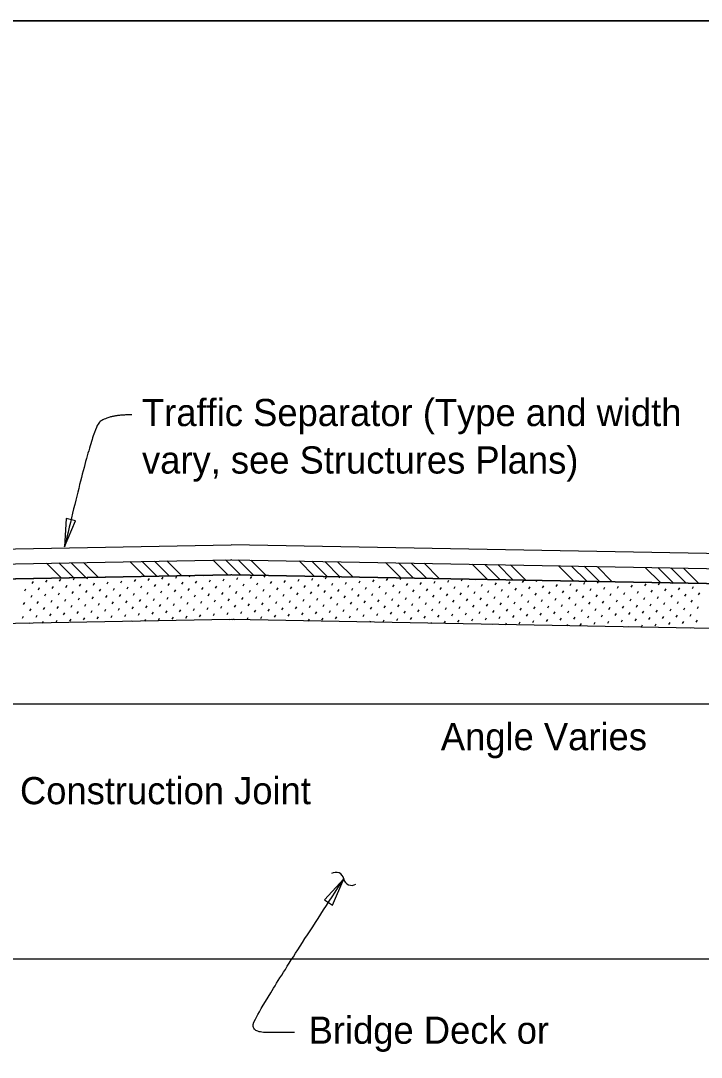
# Model space of a CAD drawing. Extents: x 0 to 15.4, y 0 to 9.7.
# Drawn here: x 7.109 to 9.001, y 6.847 to 9.73 of the extents above; entities that cross this region are included whole.
import ezdxf

# ---------------------------------------------------------------- set-up
doc = ezdxf.new("R2010")
doc.units = 0
for name, color, linetype in [('Dimension', 7, 'Continuous'), ('Miscellaneous', 7, 'Continuous'), ('Miscellaneous1', 7, 'Continuous'), ('SupstrConc', 7, 'Continuous'), ('SupstrConc_h', 7, 'Continuous'), ('TextStructures', 7, 'Continuous')]:
    doc.layers.add(name, color=color, linetype=linetype)

msp = doc.modelspace()

# ---------------------------------------------------------------- linework, layer by layer
at = {"layer": 'Dimension'}
for points in [[(7.2306, 8.266), (7.2611, 8.3391), (7.2353, 8.345)], [(8.007, 7.3426), (7.9531, 7.2845), (7.9753, 7.27)]]:
    msp.add_lwpolyline(points, close=True, dxfattribs=at)
for centre, start, end in [((7.9848, 7.3385), 10.958, 122.6852), ((8.0287, 7.347), 190.958, 302.6852)]:
    msp.add_arc(centre, 0.0224, start, end, dxfattribs=at)
for points in [[(7.4176, 8.6335), (7.3472, 8.6335), (7.3054, 8.5895), (7.2306, 8.266)], [(7.8701, 6.9155), (7.8284, 6.9155), (7.7546, 6.9155), (7.7546, 6.9572), (8.007, 7.3426)]]:
    msp.add_open_spline(points, degree=2, dxfattribs=at)
at = {"layer": 'Miscellaneous'}
for p, q in [((6.2709, 8.2042), (7.6932, 8.2305)), ((7.1801, 8.221), (7.221, 8.1801)), ((7.2144, 8.2217), (7.2554, 8.1807)), ((7.2488, 8.2223), (7.2897, 8.1814)), ((7.2831, 8.2229), (7.3241, 8.182)), ((7.4119, 8.2253), (7.4529, 8.1844)), ((7.4463, 8.226), (7.4872, 8.185)), ((7.4806, 8.2266), (7.5216, 8.1857)), ((7.515, 8.2272), (7.5559, 8.1863)), ((7.6438, 8.2296), (7.6847, 8.1887)), ((7.6781, 8.2303), (7.72, 8.1884)), ((7.6948, 8.2305), (9.1171, 8.2042)), ((7.7132, 8.2302), (7.7557, 8.1877)), ((7.7488, 8.2295), (7.7913, 8.187)), ((7.8825, 8.2271), (7.925, 8.1846)), ((7.9181, 8.2264), (7.9606, 8.1839)), ((7.9538, 8.2257), (7.9963, 8.1833)), ((7.9894, 8.2251), (8.0319, 8.1826)), ((8.1231, 8.2226), (8.1656, 8.1801)), ((8.1587, 8.2219), (8.2012, 8.1795)), ((8.1944, 8.2213), (8.2369, 8.1788)), ((8.23, 8.2206), (8.2725, 8.1781)), ((8.3637, 8.2182), (8.4062, 8.1757)), ((8.3993, 8.2175), (8.4418, 8.175)), ((7.6925, 8.1888), (6.2925, 8.1629)), ((6.2925, 8.1629), (7.6925, 8.1888)), ((9.0955, 8.1629), (7.6955, 8.1888)), ((7.6955, 8.1888), (9.0955, 8.1629)), ((8.435, 8.2168), (8.4775, 8.1743)), ((8.4706, 8.2162), (8.5131, 8.1737)), ((8.6043, 8.2137), (8.6468, 8.1712)), ((8.6399, 8.213), (8.6824, 8.1705)), ((8.6756, 8.2124), (8.7181, 8.1699)), ((8.7112, 8.2117), (8.7537, 8.1692)), ((8.8449, 8.2092), (8.8874, 8.1667)), ((8.8805, 8.2086), (8.923, 8.1661)), ((8.9162, 8.2079), (8.9587, 8.1654)), ((8.9519, 8.2073), (8.9943, 8.1648)), ((7.1404, 8.1647), (7.1437, 8.1703)), ((7.1786, 8.1679), (7.1818, 8.1735)), ((7.2167, 8.1711), (7.22, 8.1767)), ((7.2549, 8.1744), (7.2581, 8.18)), ((7.2723, 8.1569), (7.2756, 8.1625)), ((7.293, 8.1776), (7.2953, 8.1815)), ((7.3105, 8.1602), (7.3137, 8.1658)), ((7.3312, 8.1809), (7.3319, 8.1821)), ((7.3487, 8.1634), (7.3519, 8.169)), ((7.3868, 8.1666), (7.39, 8.1722)), ((7.425, 8.1699), (7.4282, 8.1755)), ((7.4631, 8.1731), (7.4664, 8.1787)), ((7.4806, 8.1557), (7.4838, 8.1613)), ((7.5013, 8.1764), (7.5045, 8.182)), ((7.5187, 8.1589), (7.522, 8.1645)), ((7.5394, 8.1796), (7.5427, 8.1852)), ((7.5569, 8.1621), (7.5601, 8.1677)), ((7.5776, 8.1828), (7.5798, 8.1867)), ((7.595, 8.1654), (7.5983, 8.171)), ((7.6157, 8.1861), (7.6165, 8.1874)), ((7.6332, 8.1686), (7.6364, 8.1742)), ((7.6713, 8.1719), (7.6746, 8.1775)), ((7.6888, 8.1544), (7.692, 8.16)), ((7.7095, 8.1751), (7.7127, 8.1807)), ((7.727, 8.1577), (7.7302, 8.1633)), ((7.7477, 8.1784), (7.7509, 8.184)), ((7.7651, 8.1609), (7.7683, 8.1665)), ((7.7858, 8.1816), (7.789, 8.1871)), ((7.8033, 8.1641), (7.8065, 8.1697)), ((7.824, 8.1848), (7.8249, 8.1864)), ((7.8414, 8.1674), (7.8447, 8.173)), ((7.8796, 8.1706), (7.8828, 8.1762)), ((7.9177, 8.1739), (7.921, 8.1795)), ((7.9352, 8.1564), (7.9384, 8.162)), ((7.9559, 8.1771), (7.9591, 8.1827)), ((7.9733, 8.1596), (7.9766, 8.1652)), ((7.994, 8.1803), (7.9957, 8.1833)), ((8.0115, 8.1629), (8.0147, 8.1685)), ((8.0496, 8.1661), (8.0529, 8.1717)), ((8.0878, 8.1694), (8.091, 8.175)), ((8.126, 8.1726), (8.1292, 8.1782)), ((8.1434, 8.1552), (8.1467, 8.1607)), ((8.1641, 8.1758), (8.1666, 8.1801)), ((8.1816, 8.1584), (8.1848, 8.164)), ((8.2023, 8.1791), (8.2025, 8.1794)), ((8.2197, 8.1616), (8.223, 8.1672)), ((8.2579, 8.1649), (8.2611, 8.1705)), ((8.296, 8.1681), (8.2993, 8.1737)), ((8.3342, 8.1714), (8.3374, 8.1769)), ((8.3723, 8.1746), (8.3733, 8.1763)), ((8.3898, 8.1571), (8.393, 8.1627)), ((8.4279, 8.1604), (8.4312, 8.166)), ((8.4661, 8.1636), (8.4693, 8.1692)), ((8.5043, 8.1669), (8.5075, 8.1725)), ((8.5424, 8.1701), (8.5441, 8.1731)), ((8.598, 8.1559), (8.6013, 8.1615)), ((8.6362, 8.1591), (8.6394, 8.1647)), ((8.6743, 8.1624), (8.6776, 8.168)), ((8.7125, 8.1656), (8.715, 8.1699)), ((8.7506, 8.1689), (8.7509, 8.1693)), ((8.8062, 8.1546), (8.8095, 8.1602)), ((8.8444, 8.1579), (8.8476, 8.1635)), ((8.8826, 8.1611), (8.8858, 8.1667)), ((8.9207, 8.1644), (8.9217, 8.1661)), ((7.1197, 8.144), (7.123, 8.1496)), ((7.1372, 8.1265), (7.1404, 8.1321)), ((7.1579, 8.1472), (7.1611, 8.1528)), ((7.1753, 8.1297), (7.1786, 8.1353)), ((7.196, 8.1504), (7.1993, 8.156)), ((7.2135, 8.133), (7.2167, 8.1386)), ((7.2342, 8.1537), (7.2374, 8.1593)), ((7.2516, 8.1362), (7.2549, 8.1418)), ((7.2898, 8.1395), (7.293, 8.1451)), ((7.328, 8.1427), (7.3312, 8.1483)), ((7.3661, 8.1459), (7.3693, 8.1515)), ((7.3836, 8.1285), (7.3868, 8.1341)), ((7.4043, 8.1492), (7.4075, 8.1548)), ((7.4217, 8.1317), (7.425, 8.1373)), ((7.4424, 8.1524), (7.4457, 8.158)), ((7.4599, 8.135), (7.4631, 8.1406)), ((7.498, 8.1382), (7.5013, 8.1438)), ((7.5362, 8.1415), (7.5394, 8.147)), ((7.5743, 8.1447), (7.5776, 8.1503)), ((7.5918, 8.1272), (7.595, 8.1328)), ((7.6125, 8.1479), (7.6157, 8.1535)), ((7.6299, 8.1305), (7.6332, 8.1361)), ((7.6506, 8.1512), (7.6539, 8.1568)), ((7.6681, 8.1337), (7.6713, 8.1393)), ((7.7063, 8.137), (7.7095, 8.1426)), ((7.7444, 8.1402), (7.7477, 8.1458)), ((7.7826, 8.1434), (7.7858, 8.149)), ((7.8, 8.126), (7.8033, 8.1316)), ((7.8207, 8.1467), (7.824, 8.1523)), ((7.8382, 8.1292), (7.8414, 8.1348)), ((7.8589, 8.1499), (7.8621, 8.1555)), ((7.8763, 8.1325), (7.8796, 8.1381)), ((7.897, 8.1532), (7.9003, 8.1588)), ((7.9145, 8.1357), (7.9177, 8.1413)), ((7.9526, 8.1389), (7.9559, 8.1445)), ((7.9908, 8.1422), (7.994, 8.1478)), ((8.0289, 8.1454), (8.0322, 8.151)), ((8.0464, 8.128), (8.0496, 8.1336)), ((8.0671, 8.1487), (8.0703, 8.1543)), ((8.0846, 8.1312), (8.0878, 8.1368)), ((8.1053, 8.1519), (8.1085, 8.1575)), ((8.1227, 8.1345), (8.126, 8.1401)), ((8.1609, 8.1377), (8.1641, 8.1433)), ((8.199, 8.1409), (8.2023, 8.1465)), ((8.2372, 8.1442), (8.2404, 8.1498)), ((8.2546, 8.1267), (8.2579, 8.1323)), ((8.2753, 8.1474), (8.2786, 8.153)), ((8.2928, 8.13), (8.296, 8.1356)), ((8.3135, 8.1507), (8.3167, 8.1563)), ((8.3309, 8.1332), (8.3342, 8.1388)), ((8.3516, 8.1539), (8.3549, 8.1595)), ((8.3691, 8.1364), (8.3723, 8.142)), ((8.4072, 8.1397), (8.4105, 8.1453)), ((8.4454, 8.1429), (8.4486, 8.1485)), ((8.4629, 8.1255), (8.4661, 8.1311)), ((8.4836, 8.1462), (8.4868, 8.1518)), ((8.501, 8.1287), (8.5043, 8.1343)), ((8.5217, 8.1494), (8.525, 8.155)), ((8.5392, 8.1319), (8.5424, 8.1375)), ((8.5599, 8.1526), (8.5631, 8.1582)), ((8.5773, 8.1352), (8.5806, 8.1408)), ((8.6155, 8.1384), (8.6187, 8.144)), ((8.6536, 8.1417), (8.6569, 8.1473)), ((8.6918, 8.1449), (8.695, 8.1505)), ((8.7092, 8.1275), (8.7125, 8.1331)), ((8.7299, 8.1482), (8.7332, 8.1538)), ((8.7474, 8.1307), (8.7506, 8.1363)), ((8.7681, 8.1514), (8.7713, 8.157)), ((8.7856, 8.1339), (8.7888, 8.1395)), ((8.8237, 8.1372), (8.8269, 8.1428)), ((8.8619, 8.1404), (8.8651, 8.146)), ((8.9, 8.1437), (8.9033, 8.1493)), ((8.9175, 8.1262), (8.9207, 8.1318)), ((8.9382, 8.1469), (8.9414, 8.1525)), ((8.9556, 8.1294), (8.9589, 8.135)), ((8.9763, 8.1501), (8.9796, 8.1557)), ((8.9938, 8.1327), (8.997, 8.1383)), ((7.1165, 8.1058), (7.1197, 8.1114)), ((7.1546, 8.109), (7.1579, 8.1146)), ((7.1928, 8.1123), (7.196, 8.1179)), ((7.2309, 8.1155), (7.2342, 8.1211)), ((7.2484, 8.0981), (7.2516, 8.1037)), ((7.2691, 8.1188), (7.2723, 8.1244)), ((7.2866, 8.1013), (7.2898, 8.1069)), ((7.3073, 8.122), (7.3105, 8.1276)), ((7.3247, 8.1045), (7.328, 8.1101)), ((7.3454, 8.1252), (7.3487, 8.1308)), ((7.3629, 8.1078), (7.3661, 8.1134)), ((7.401, 8.111), (7.4043, 8.1166)), ((7.4392, 8.1143), (7.4424, 8.1199)), ((7.4566, 8.0968), (7.4599, 8.1024)), ((7.4773, 8.1175), (7.4806, 8.1231)), ((7.4948, 8.1001), (7.498, 8.1057)), ((7.5155, 8.1208), (7.5187, 8.1264)), ((7.5329, 8.1033), (7.5362, 8.1089)), ((7.5536, 8.124), (7.5569, 8.1296)), ((7.5711, 8.1065), (7.5743, 8.1121)), ((7.6092, 8.1098), (7.6125, 8.1154)), ((7.6474, 8.113), (7.6506, 8.1186)), ((7.6856, 8.1163), (7.6888, 8.1219)), ((7.703, 8.0988), (7.7063, 8.1044)), ((7.7237, 8.1195), (7.727, 8.1251)), ((7.7412, 8.102), (7.7444, 8.1076)), ((7.7619, 8.1227), (7.7651, 8.1283)), ((7.7793, 8.1053), (7.7826, 8.1109)), ((7.8175, 8.1085), (7.8207, 8.1141)), ((7.8556, 8.1118), (7.8589, 8.1174)), ((7.8938, 8.115), (7.897, 8.1206)), ((7.9112, 8.0976), (7.9145, 8.1031)), ((7.9319, 8.1182), (7.9352, 8.1238)), ((7.9494, 8.1008), (7.9526, 8.1064)), ((7.9701, 8.1215), (7.9733, 8.1271)), ((7.9876, 8.104), (7.9908, 8.1096)), ((8.0082, 8.1247), (8.0115, 8.1303)), ((8.0257, 8.1073), (8.0289, 8.1129)), ((8.0639, 8.1105), (8.0671, 8.1161)), ((8.102, 8.1138), (8.1053, 8.1194)), ((8.1402, 8.117), (8.1434, 8.1226)), ((8.1576, 8.0995), (8.1609, 8.1051)), ((8.1783, 8.1202), (8.1816, 8.1258)), ((8.1958, 8.1028), (8.199, 8.1084)), ((8.2165, 8.1235), (8.2197, 8.1291)), ((8.2339, 8.106), (8.2372, 8.1116)), ((8.2721, 8.1093), (8.2753, 8.1149)), ((8.3102, 8.1125), (8.3135, 8.1181)), ((8.3484, 8.1157), (8.3516, 8.1213)), ((8.3659, 8.0983), (8.3691, 8.1039)), ((8.3866, 8.119), (8.3898, 8.1246)), ((8.404, 8.1015), (8.4072, 8.1071)), ((8.4247, 8.1222), (8.4279, 8.1278)), ((8.4422, 8.1048), (8.4454, 8.1104)), ((8.4803, 8.108), (8.4836, 8.1136)), ((8.5185, 8.1113), (8.5217, 8.1168)), ((8.5566, 8.1145), (8.5599, 8.1201)), ((8.5741, 8.097), (8.5773, 8.1026)), ((8.5948, 8.1177), (8.598, 8.1233)), ((8.6122, 8.1003), (8.6155, 8.1059)), ((8.6329, 8.121), (8.6362, 8.1266)), ((8.6504, 8.1035), (8.6536, 8.1091)), ((8.6711, 8.1242), (8.6743, 8.1298)), ((8.6885, 8.1068), (8.6918, 8.1124)), ((8.7267, 8.11), (8.7299, 8.1156)), ((8.7649, 8.1132), (8.7681, 8.1188)), ((8.803, 8.1165), (8.8062, 8.1221)), ((8.8205, 8.099), (8.8237, 8.1046)), ((8.8412, 8.1197), (8.8444, 8.1253)), ((8.8586, 8.1023), (8.8619, 8.1079)), ((8.8793, 8.123), (8.8826, 8.1286)), ((8.8968, 8.1055), (8.9, 8.1111)), ((8.9349, 8.1087), (8.9382, 8.1143)), ((8.9731, 8.112), (8.9763, 8.1176)), ((7.1132, 8.0676), (7.1165, 8.0732)), ((7.1339, 8.0883), (7.1372, 8.0939)), ((7.1514, 8.0709), (7.1546, 8.0765)), ((7.1721, 8.0916), (7.1753, 8.0972)), ((7.1896, 8.0741), (7.1928, 8.0797)), ((7.2102, 8.0948), (7.2135, 8.1004)), ((7.2277, 8.0774), (7.2309, 8.083)), ((7.2659, 8.0806), (7.2691, 8.0862)), ((7.304, 8.0839), (7.3073, 8.0894)), ((7.3422, 8.0871), (7.3454, 8.0927)), ((7.3596, 8.0696), (7.3629, 8.0752)), ((7.3803, 8.0903), (7.3836, 8.0959)), ((7.3978, 8.0729), (7.401, 8.0785)), ((7.4185, 8.0936), (7.4217, 8.0992)), ((7.4359, 8.0761), (7.4392, 8.0817)), ((7.4741, 8.0794), (7.4773, 8.085)), ((7.5122, 8.0826), (7.5155, 8.0882)), ((7.5504, 8.0858), (7.5536, 8.0914)), ((7.5679, 8.0684), (7.5711, 8.074)), ((7.5886, 8.0891), (7.5918, 8.0947)), ((7.606, 8.0716), (7.6092, 8.0772)), ((7.6267, 8.0923), (7.6299, 8.0979)), ((7.6442, 8.0749), (7.6474, 8.0805)), ((7.6649, 8.0956), (7.6681, 8.1012)), ((7.6823, 8.0781), (7.6856, 8.0837)), ((7.7205, 8.0813), (7.7237, 8.0869)), ((7.7586, 8.0846), (7.7619, 8.0902)), ((7.7968, 8.0878), (7.8, 8.0934)), ((7.8142, 8.0704), (7.8175, 8.076)), ((7.8349, 8.0911), (7.8382, 8.0967)), ((7.8524, 8.0736), (7.8556, 8.0792)), ((7.8731, 8.0943), (7.8763, 8.0999)), ((7.8905, 8.0769), (7.8938, 8.0825)), ((7.9287, 8.0801), (7.9319, 8.0857)), ((7.9669, 8.0833), (7.9701, 8.0889)), ((8.005, 8.0866), (8.0082, 8.0922)), ((8.0225, 8.0691), (8.0257, 8.0747)), ((8.0432, 8.0898), (8.0464, 8.0954)), ((8.0606, 8.0724), (8.0639, 8.078)), ((8.0813, 8.0931), (8.0846, 8.0987)), ((8.0988, 8.0756), (8.102, 8.0812)), ((8.1195, 8.0963), (8.1227, 8.1019)), ((8.1369, 8.0788), (8.1402, 8.0844)), ((8.1751, 8.0821), (8.1783, 8.0877)), ((8.2132, 8.0853), (8.2165, 8.0909)), ((8.2307, 8.0679), (8.2339, 8.0735)), ((8.2514, 8.0886), (8.2546, 8.0942)), ((8.2688, 8.0711), (8.2721, 8.0767)), ((8.2895, 8.0918), (8.2928, 8.0974)), ((8.307, 8.0743), (8.3102, 8.0799)), ((8.3277, 8.095), (8.3309, 8.1006)), ((8.3452, 8.0776), (8.3484, 8.0832)), ((8.3833, 8.0808), (8.3866, 8.0864)), ((8.4215, 8.0841), (8.4247, 8.0897)), ((8.4596, 8.0873), (8.4629, 8.0929)), ((8.4771, 8.0699), (8.4803, 8.0755)), ((8.4978, 8.0906), (8.501, 8.0962)), ((8.5152, 8.0731), (8.5185, 8.0787)), ((8.5359, 8.0938), (8.5392, 8.0994)), ((8.5534, 8.0763), (8.5566, 8.0819)), ((8.5915, 8.0796), (8.5948, 8.0852)), ((8.6297, 8.0828), (8.6329, 8.0884)), ((8.6678, 8.0861), (8.6711, 8.0917)), ((8.6853, 8.0686), (8.6885, 8.0742)), ((8.706, 8.0893), (8.7092, 8.0949)), ((8.7235, 8.0718), (8.7267, 8.0774)), ((8.7442, 8.0925), (8.7474, 8.0981)), ((8.7616, 8.0751), (8.7649, 8.0807)), ((8.7823, 8.0958), (8.7856, 8.1014)), ((8.7998, 8.0783), (8.803, 8.0839)), ((8.8379, 8.0816), (8.8412, 8.0872)), ((8.8761, 8.0848), (8.8793, 8.0904)), ((8.9142, 8.088), (8.9175, 8.0936)), ((8.9317, 8.0706), (8.9349, 8.0762)), ((8.9524, 8.0913), (8.9556, 8.0969)), ((8.9698, 8.0738), (8.9731, 8.0794)), ((8.9905, 8.0945), (8.9938, 8.1001)), ((7.6901, 8.0638), (6.3571, 8.0391)), ((7.1326, 8.0534), (7.1339, 8.0558)), ((7.1692, 8.0541), (7.1721, 8.059)), ((7.207, 8.0567), (7.2102, 8.0623)), ((7.2452, 8.0599), (7.2484, 8.0655)), ((7.2833, 8.0632), (7.2866, 8.0688)), ((7.3215, 8.0664), (7.3247, 8.072)), ((7.4171, 8.0587), (7.4185, 8.061)), ((7.4538, 8.0594), (7.4566, 8.0643)), ((7.4915, 8.0619), (7.4948, 8.0675)), ((7.5297, 8.0651), (7.5329, 8.0707)), ((9.0309, 8.0391), (7.6979, 8.0638)), ((7.7015, 8.0637), (7.703, 8.0662)), ((7.7379, 8.0639), (7.7412, 8.0695)), ((7.7761, 8.0671), (7.7793, 8.0727)), ((7.8724, 8.0605), (7.8731, 8.0618)), ((7.9083, 8.0599), (7.9112, 8.065)), ((7.9462, 8.0626), (7.9494, 8.0682)), ((7.9843, 8.0659), (7.9876, 8.0715)), ((8.0791, 8.0567), (8.0813, 8.0605)), ((8.1162, 8.0581), (8.1195, 8.0637)), ((8.1544, 8.0614), (8.1576, 8.067)), ((8.1925, 8.0646), (8.1958, 8.0702)), ((8.25, 8.0535), (8.2514, 8.056)), ((8.2863, 8.0537), (8.2895, 8.0592)), ((8.3245, 8.0569), (8.3277, 8.0625)), ((8.3626, 8.0601), (8.3659, 8.0657)), ((8.4008, 8.0634), (8.404, 8.069)), ((8.4208, 8.0504), (8.4215, 8.0515)), ((8.4389, 8.0666), (8.4422, 8.0722)), ((8.4567, 8.0497), (8.4596, 8.0548)), ((8.4945, 8.0524), (8.4978, 8.058)), ((8.5327, 8.0556), (8.5359, 8.0612)), ((8.5708, 8.0589), (8.5741, 8.0645)), ((8.609, 8.0621), (8.6122, 8.0677)), ((8.6275, 8.0465), (8.6297, 8.0503)), ((8.6471, 8.0654), (8.6504, 8.071)), ((8.6646, 8.0479), (8.6678, 8.0535)), ((8.7028, 8.0511), (8.706, 8.0567)), ((8.7409, 8.0544), (8.7442, 8.06)), ((8.7791, 8.0576), (8.7823, 8.0632)), ((8.7984, 8.0434), (8.7998, 8.0458)), ((8.8172, 8.0609), (8.8205, 8.0665)), ((8.8347, 8.0434), (8.8379, 8.049)), ((8.8554, 8.0641), (8.8586, 8.0697)), ((8.8728, 8.0467), (8.8761, 8.0523)), ((8.8935, 8.0674), (8.8968, 8.0729)), ((8.911, 8.0499), (8.9142, 8.0555)), ((8.9491, 8.0531), (8.9524, 8.0587)), ((8.9873, 8.0564), (8.9905, 8.062)), ((8.9692, 8.0402), (8.9698, 8.0413))]:
    msp.add_line(p, q, dxfattribs=at)
msp.add_lwpolyline([(0, 0), (15.394, 0), (15.394, 9.7298), (0, 9.7298)], close=True, dxfattribs=at)
for centre, radius in [((7.694, 8.1889), 0.0417), ((7.694, 8.1055), 0.0833), ((7.694, 7.8555), 0.2083)]:
    msp.add_arc(centre, radius, 88.9384, 91.0616, dxfattribs=at)
at = {"layer": 'Miscellaneous1'}
msp.add_lwpolyline([(0, 9.7298), (15.394, 9.7298), (15.394, 0), (0, 0)], close=True, dxfattribs=at)
at = {"layer": 'SupstrConc'}
for p, q in [((6.7133, 8.2541), (7.694, 8.2723)), ((9.1386, 8.2455), (7.694, 8.2722)), ((5.2525, 7.1204), (10.1384, 7.1204))]:
    msp.add_line(p, q, dxfattribs=at)
at = {"layer": 'SupstrConc_h'}
msp.add_lwpolyline([(9.1761, 7.8288), (5.5626, 7.8288)], dxfattribs=at)

# ---------------------------------------------------------------- texts
at = {"layer": 'Dimension'}
for s, p in [('Traffic Separator (Type and width ', (7.4458, 8.6022)), ('vary, see Structures Plans)', (7.4458, 8.4702)), ('Bridge Deck or ', (7.9092, 6.8841))]:
    msp.add_text(s, height=0.0756, dxfattribs=at).set_placement(p)
at = {"layer": 'TextStructures'}
for s, p in [('Angle Varies', (8.2768, 7.7007)), ('Construction Joint', (7.1064, 7.5504))]:
    msp.add_text(s, height=0.0756, dxfattribs=at).set_placement(p)

doc.saveas('drawing.dxf')
